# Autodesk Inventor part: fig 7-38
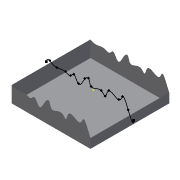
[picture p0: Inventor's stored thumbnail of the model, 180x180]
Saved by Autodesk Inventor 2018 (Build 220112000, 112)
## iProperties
Shininess: 64.0
Length Units: 11269
Angle Units: 11279
Time Units: 11290
Mass Units: 11283
Length Display Precision: 3
Angle Display Precision: 2
Compacted: True
Part Number: fig 7-38
Document SubType Name: Modeling
Created: 2002-12
Designer: deepak
Density: 1 g/cm^3
Material: Generic
Appearance: Default
Density: 0.0
Volumn: 0.0
Area: 0.0
PropertySet Name: Model Information
Control State: 0
Master: False
Checked Out: False
Author: cadcim
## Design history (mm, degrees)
sketch "Sketch1"
  geometry: L1 (-32.188, 30.089)-(27.812, 30.089); L2 (27.812, 30.089)-(27.812, -29.911); L3 (27.812, -29.911)-(-32.188, -29.911); L4 (-32.188, -29.911)-(-32.188, 30.089)
  constraints: 8 end point, 2 parallel, 1 horizontal, 1 perpendicular
  dimensions: "d0" = 60 distance of L1.start L1.end; "d1" = 60 distance of L3.end L1.start
extrude "Extrusion1" new body sketch "Sketch1" stored distance "d2" = 20; taper "d3" = 0 deg
sketch "Sketch2"
  geometry: 17 further points
  constraints: 17 other
extrude_surface "ExtrusionSrf1" sketch "Sketch2" dims "d4" = 70, "d5" = 0
split "Split1"
delete_face "Delete Face1"
node "Sketch5"
sketch "Sketch6"
  geometry: 1 further point
body "Srf1"
body "Srf2"
